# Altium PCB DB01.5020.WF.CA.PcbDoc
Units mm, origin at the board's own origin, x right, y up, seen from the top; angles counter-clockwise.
Board outline 46 x 20 mm, 2 copper layers (Top Layer, Bottom Layer); 3 components, 2 nets, 10 pads, 146 vias.
Unrouted connection lines stored in the file: 1.
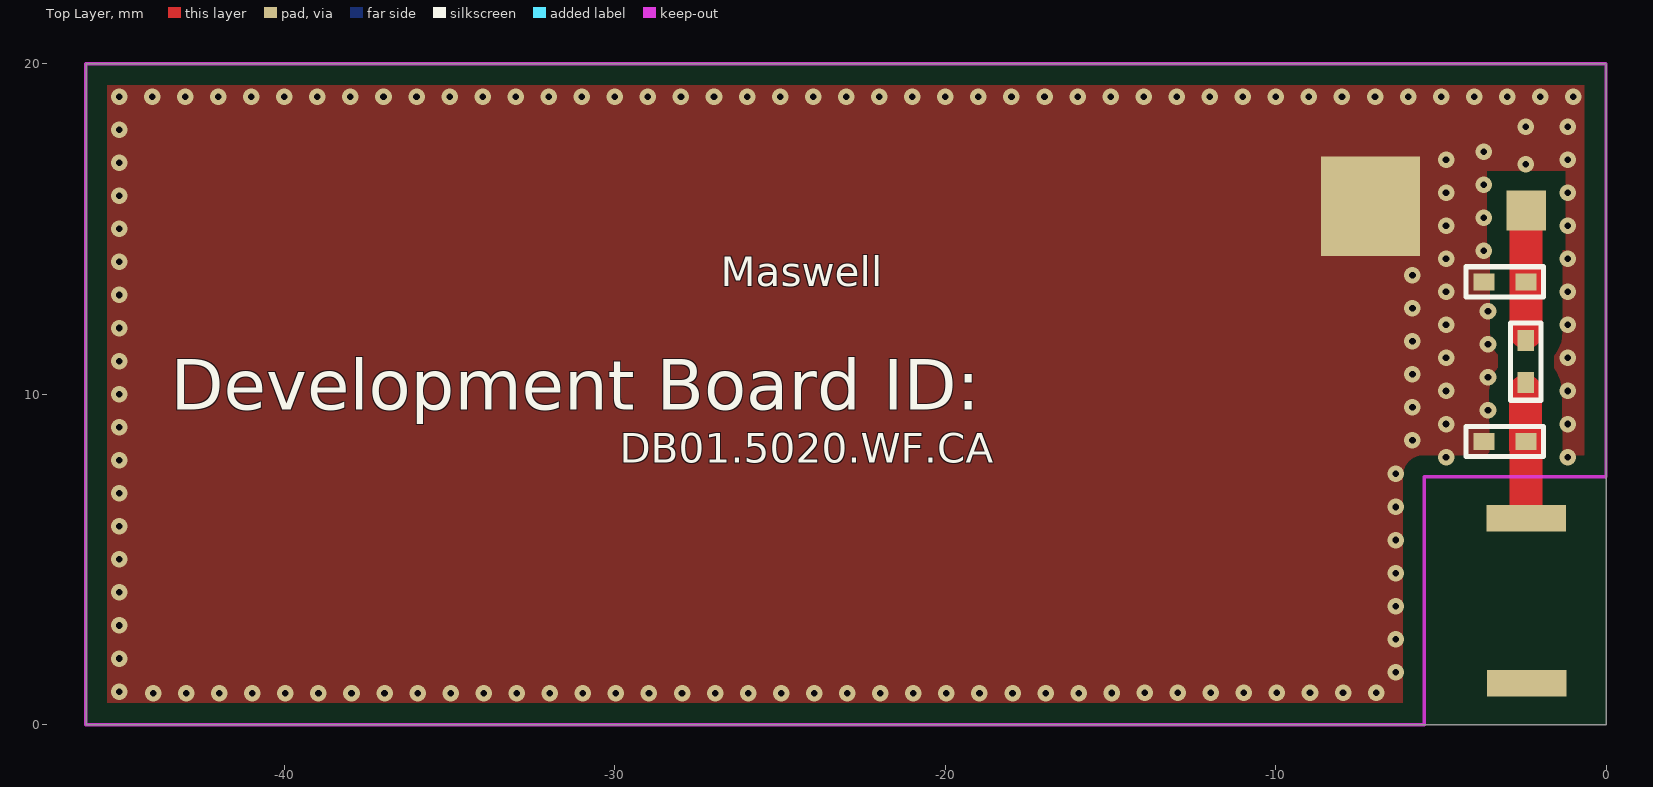
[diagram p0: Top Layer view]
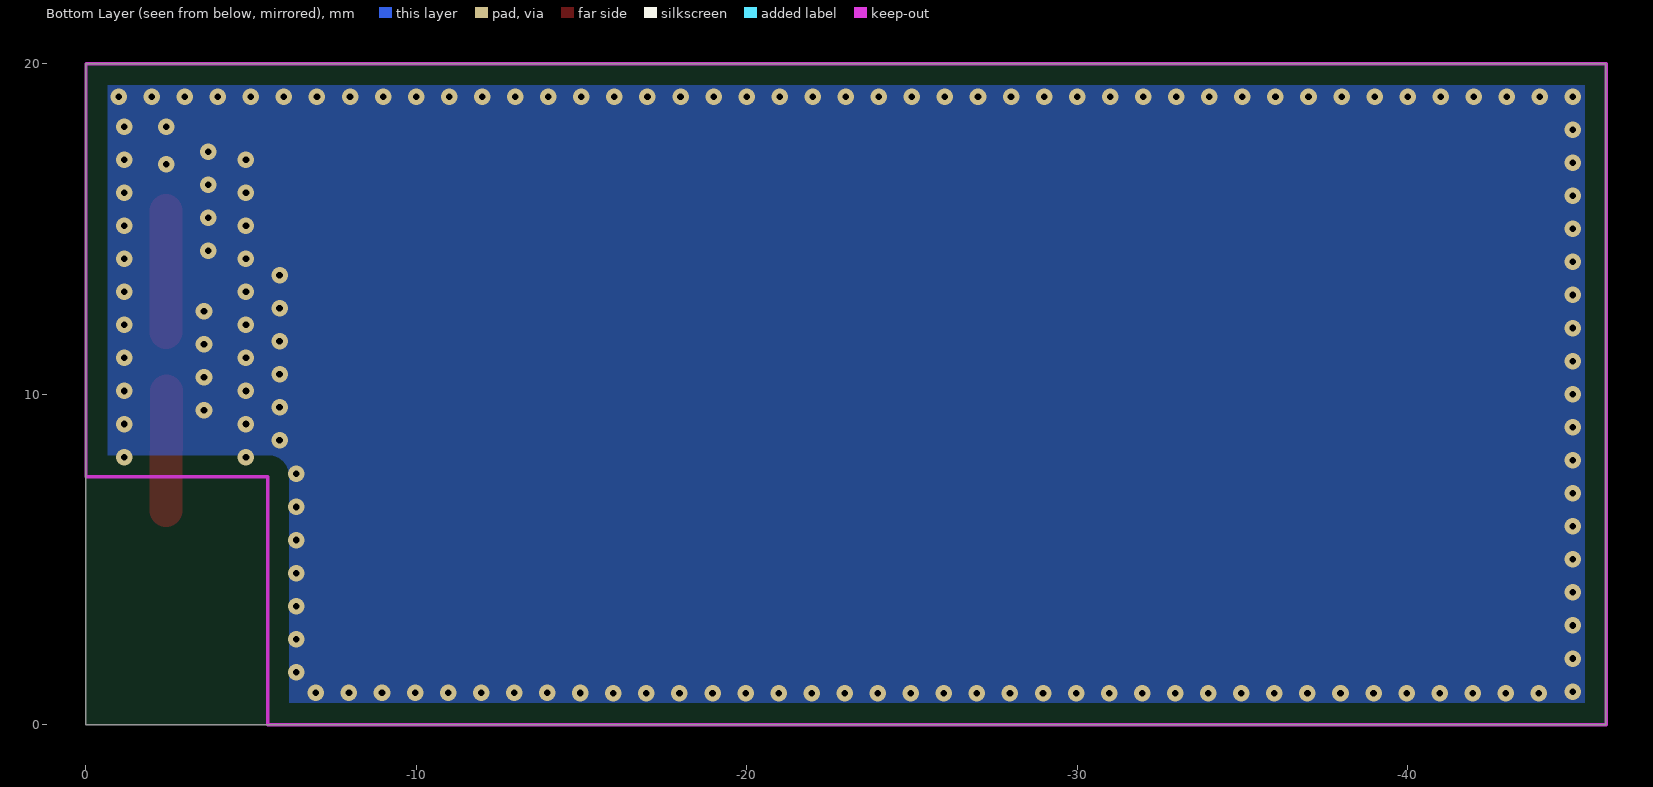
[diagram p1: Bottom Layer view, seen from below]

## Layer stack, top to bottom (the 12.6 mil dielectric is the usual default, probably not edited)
Top Solder: solder mask 0.0102, Solder Resist, Dk 3.5
Top Layer: signal copper 0.0356
Dielectric1: dielectric 0.32, FR-4, Dk 4.8
Bottom Layer: signal copper 0.0356
Bottom Solder: solder mask 0.0102, Solder Resist, Dk 3.5

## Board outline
-46,0 -46,20 0,20 0,0

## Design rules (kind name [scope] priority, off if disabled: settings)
Clearance [All] p1: gap=0.6
PlaneConnect [All] p1: planeconnectstyle=Direct reliefexpansion=0.508 reliefentries=4 reliefconductorwidth=0.254 reliefairgap=0.254
PolygonConnect [All] p1: connectstyle=Direct reliefconductorwidth=0.254 reliefentries=4 polygonreliefangle="90 Angle" airgapwidth=0.254
RoutingVias [All] p1: holewidth=0.711 width=1.27 viastyle="Through Hole" minholewidth=0.711 minwidth=1.27 maxholewidth=0.711 maxwidth=1.27
SilkToSolderMaskClearance SilkscreenOverComponentPads [IsPad] p1: minsilkscreentomaskgap=0.254 clearancetoexposedcopper=TRUE
SolderMaskExpansion [All] p1: expansion=0.102
Width [All] p1: maxlimit=1 minlimit=1 preferedwidth=1
28 further rules are at their usual default settings.

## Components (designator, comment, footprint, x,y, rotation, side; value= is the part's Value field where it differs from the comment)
? "" 0402s -2.439,10.348 r90 top
? "" 0402s -2.439,13.396 r180 top
? "" 0402s -2.439,8.57 r180 top

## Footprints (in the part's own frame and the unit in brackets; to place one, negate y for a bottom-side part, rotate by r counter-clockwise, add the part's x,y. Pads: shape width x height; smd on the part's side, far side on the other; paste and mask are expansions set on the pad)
0402s [mil]
  rect 25x20 smd: 1(0,0) 2(50,0)
  silkscreen extent -21,-18 71,18

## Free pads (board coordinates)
  rect 3x3 smd mask+0.102: 0(-7.138,15.682)
  rect 2.4x0.8 smd mask+0: 0(-2.426,6.25) 0(-2.413,1.25)
  rect 1.2x1.2 smd: 0(-2.426,15.555)

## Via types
v1: diameter 0.5, hole 0.2, Top Layer to Bottom Layer, 146 vias

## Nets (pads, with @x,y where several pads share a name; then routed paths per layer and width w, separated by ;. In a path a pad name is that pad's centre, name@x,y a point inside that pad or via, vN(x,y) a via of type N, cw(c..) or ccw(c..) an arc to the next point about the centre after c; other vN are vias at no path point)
GND: ?.2@-3.709,8.57 ?.2@-3.709,13.396 pad.0@-7.138,15.682
  other v1: -43.968,0.95 -42.968,0.95 -41.968,0.95 -40.968,0.95 -39.968,0.95 -38.968,0.95 -37.968,0.95 -36.968,0.95 -35.968,0.95 -34.968,0.95 -33.968,0.95 -32.968,0.95 -31.968,0.95 -30.968,0.95 -29.968,0.95 -28.968,0.95 -27.968,0.95 -26.968,0.95 -25.968,0.95 -24.968,0.95 -23.968,0.95 -22.968,0.95 -21.968,0.95 -20.968,0.95 -19.968,0.95 -18.968,0.95 -17.968,0.95 -16.968,0.95 -15.968,0.95 -14.968,0.95 -14.968,0.966 -13.968,0.966 -12.968,0.966 -11.968,0.966 -10.968,0.966 -9.968,0.966 -8.968,0.966 -7.968,0.966 -6.968,0.966 -45,1 -6.376,1.585 -45,2 -6.376,2.585 -45,3 -6.376,3.585 -45,4 -6.376,4.585 -45,5 -6.376,5.585 -45,6 -6.376,6.585 -45,7 -6.376,7.585 -45,8 -4.852,8.095 -1.169,8.095 -5.868,8.602 -45,9 -4.852,9.095 -1.169,9.095 -3.582,9.507 -5.868,9.602 -45,10 -4.852,10.095 -1.169,10.095 -3.582,10.507 -5.868,10.602 -45,11 -4.852,11.095 -1.169,11.095 -3.582,11.507 -5.868,11.602 -45,12 -4.852,12.095 -1.169,12.095 -3.582,12.507 -5.868,12.602 -45,13 -4.852,13.095 -1.169,13.095 -5.868,13.602 -45,14 -4.852,14.095 -1.169,14.095 -3.709,14.333 -45,15 -4.852,15.095 -1.169,15.095 -3.709,15.333 -45,16 -4.852,16.095 -1.169,16.095 -3.709,16.333 -2.439,16.952 -45,17 -4.852,17.095 -1.169,17.095 -3.709,17.333 -45,18 -2.439,18.095 -1.169,18.095 -45,19 -44,19 -43,19 -42,19 -41,19 -40,19 -39,19 -38,19 -37,19 -36,19 -35,19 -34,19 -33,19 -32,19 -31,19 -30,19 -29,19 -28,19 -27,19 -26,19 -25,19 -24,19 -23,19 -22,19 -21,19 -20,19 -19,19 -18,19 -17,19 -16,19 -15,19 -14,19 -13,19 -12,19 -11,19 -10,19 -9,19 -8,19 -7,19 -6,19 -5,19 -4,19 -3,19 -2,19 -1,19
RF: ?.1 ?.2@-2.439,11.618 pad.0@-2.426,6.25 pad.0@-2.426,15.555 | length 7.3
  Top Layer w1: ?.1@-2.445,10.094 pad.0@-2.431,6.477 ; ?.2@-2.426,11.872 pad.0@-2.426,15.555

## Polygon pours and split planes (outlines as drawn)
GND on Top Layer "BottomLayer-GND" (solid, remove dead copper, pour order 1003): -49.175,20.91 1.625,20.91 1.625,-1.061 -48.399,-1.061 -48.399,20.148 -49.175,20.91
GND on Bottom Layer "BottomLayer-GND" (solid, remove dead copper, pour order 1002): -48.54,21.524 2.26,21.524 2.26,-0.447 -47.764,-0.447 -47.764,20.762 -48.54,21.524

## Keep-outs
Keep-Out Layer:
  lines w0.1: -46.013,0 -5.513,0 -5.513,7.5 -0.013,7.5 -0.013,20 -46.013,20 -46.013,0

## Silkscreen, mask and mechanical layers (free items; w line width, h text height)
Top Overlay:
  text "Maswell" at -26.797,12.954 h1.52
  text "Development Board ID:" at -43.434,9.525 h1.52
  text "DB01.5020.WF.CA" at -29.845,7.62 h1.52
Mechanical 1:
  lines w0.1: -46,0 -5.5,0 0,0 0,7.5 0,20 -46,20 -46,0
